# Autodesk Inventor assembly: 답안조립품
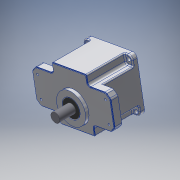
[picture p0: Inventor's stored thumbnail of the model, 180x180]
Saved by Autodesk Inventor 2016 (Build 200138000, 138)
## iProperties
Created: 2017-01
Part Number: 답안조립품
Material: 일반
Document SubType Name: Assembly
Designer: Owner
Author: Owner
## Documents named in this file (10)
- C:\Users\Owner\Desktop\470111V1010\답안조립품.iam
- C:\Users\Owner\Desktop\470111V1010\본체.ipt
- C:\Users\Owner\Desktop\470111V1010\메인축.ipt
- C:\Users\Owner\Desktop\470111V1010\베어링 608.ipt
- C:\Users\Owner\Desktop\470111V1010\베어링 6003.ipt
- C:\Users\Owner\Desktop\470111V1010\볼트 M4 x 10.ipt
- C:\Users\Owner\Desktop\470111V1010\서브축.ipt
- C:\Users\Owner\Desktop\470111V1010\오일실 8 22 7.ipt
- C:\Users\Owner\Desktop\470111V1010\오일실 17 32 8.ipt
- C:\Users\Owner\Desktop\470111V1010\커버.ipt
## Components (2 placed, 1 different names)
1. ISO 4762 M4 x 10:1
2. ISO 4762 M4 x 10:2
